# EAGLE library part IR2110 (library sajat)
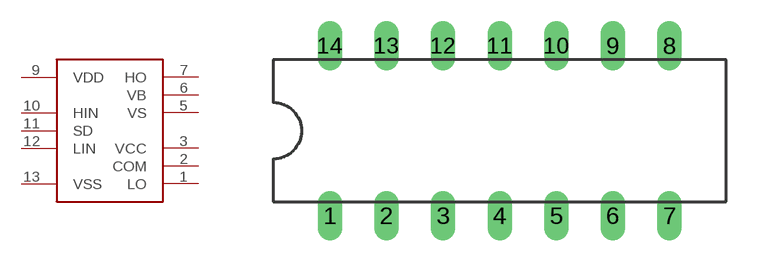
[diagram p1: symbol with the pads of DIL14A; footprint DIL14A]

Designator prefix -

## IR2110  [DIL14A]
1  LO  out
2  COM  pwr
3  VCC  pwr
5  VS
6  VB  pwr
7  HO  out
9  VDD  pwr
10  HIN  in
11  SD  in
12  LIN  in
13  VSS  pwr

## Footprint DIL14A (pad centres in mm)
drill 0.6 pad 1.016 long: 1 -7.62,-3.81; 2 -5.08,-3.81; 3 -2.54,-3.81; 4 0,-3.81; 5 2.54,-3.81; 6 5.08,-3.81; 7 7.62,-3.81; 8 7.62,3.81; 9 5.08,3.81; 10 2.54,3.81; 11 0,3.81; 12 -2.54,3.81; 13 -5.08,3.81; 14 -7.62,3.81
